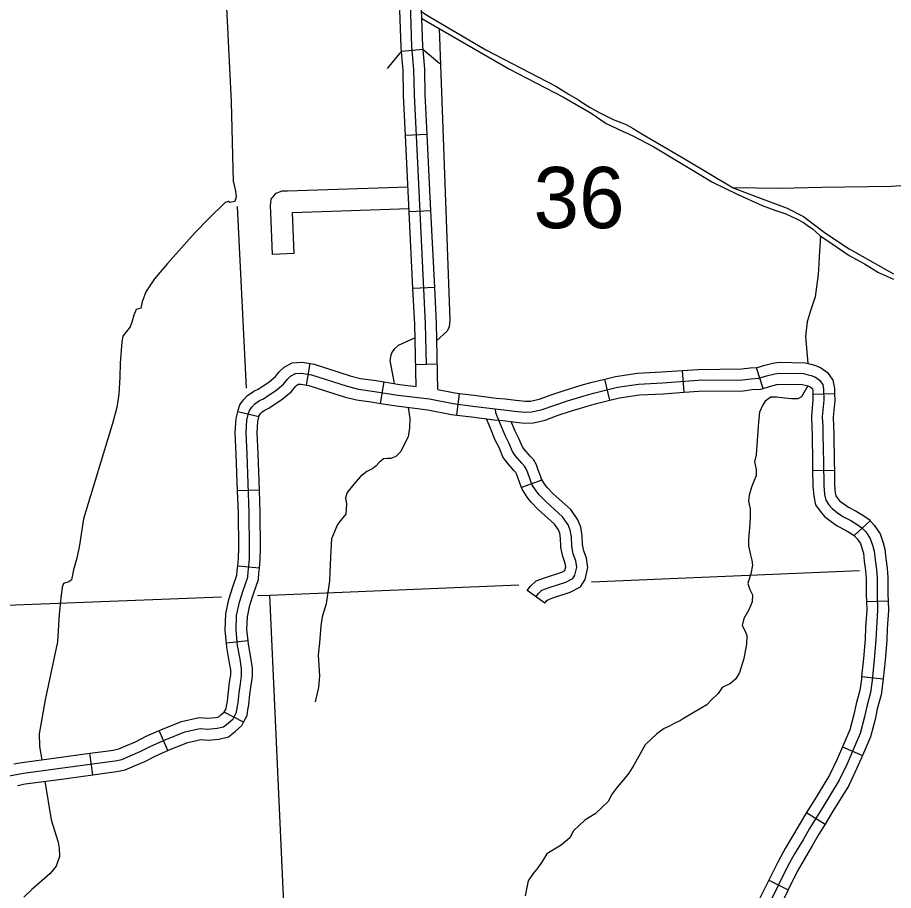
# Model space of a CAD drawing. Extents: x -5566 to 1759129, y -3726 to 731467.
# Drawn here: x -4703.72 to -4657.85, y 261.21 to 306.9 of the extents above; entities that cross this region are included whole.
import ezdxf

# ---------------------------------------------------------------- set-up
doc = ezdxf.new("R2010")
doc.units = 0
doc.layers.add('Default', color=7, linetype='Continuous')

msp = doc.modelspace()

# ---------------------------------------------------------------- linework, layer by layer
at = {"layer": 'Default'}
for p, q in [((-4682.48, 305.221), (-4683.614, 305.116)), ((-4682.265, 300.782), (-4683.403, 300.727)), ((-4682.069, 296.778), (-4683.207, 296.721)), ((-4681.871, 292.773), (-4683.009, 292.716)), ((-4688.588, 287.665), (-4688.394, 288.788)), ((-4681.731, 288.75), (-4682.87, 288.725)), ((-4664.673, 287.487), (-4665.023, 288.571)), ((-4668.808, 287.29), (-4668.89, 288.426)), ((-4684.702, 286.701), (-4684.52, 287.825)), ((-4672.692, 286.871), (-4672.963, 287.977)), ((-4680.72, 286.091), (-4680.579, 287.221)), ((-4662.073, 287.193), (-4660.934, 287.217)), ((-4691.08, 286.006), (-4692.189, 286.267)), ((-4662.081, 283.192), (-4660.942, 283.208)), ((-4676.258, 282.692), (-4677.329, 282.304)), ((-4691.054, 282.16), (-4692.193, 282.119)), ((-4659.904, 279.79), (-4659.061, 280.556)), ((-4691.047, 278.078), (-4692.181, 278.187)), ((-4676.109, 276.237), (-4677.032, 276.903)), ((-4659.263, 276.325), (-4658.125, 276.368)), ((-4691.646, 274.273), (-4692.779, 274.159)), ((-4659.513, 272.405), (-4658.38, 272.291)), ((-4691.884, 270.014), (-4692.892, 270.544)), ((-4695.841, 268.537), (-4696.304, 269.578)), ((-4699.772, 267.262), (-4699.924, 268.391)), ((-4660.514, 268.724), (-4659.471, 268.266)), ((-4662.398, 265.284), (-4661.429, 264.685)), ((-4664.381, 261.742), (-4663.361, 261.234))]:
    msp.add_line(p, q, dxfattribs=at)
for points in [[(-4692.402, 298.29), (-4692.51, 302.48), (-4692.946, 311.325), (-4692.964, 312.125), (-4692.875, 312.516)], [(-4683.577, 304.707), (-4683.633, 305.325), (-4683.728, 308.29), (-4683.736, 308.755)], [(-4682.301, 288.738), (-4682.348, 290.874), (-4682.763, 299.284), (-4682.935, 302.855), (-4682.956, 304.175), (-4683.065, 305.36), (-4683.159, 308.304), (-4683.172, 309.079)], [(-4682.442, 304.811), (-4682.496, 305.395), (-4682.59, 308.318), (-4682.597, 308.774)], [(-4682.554, 307.198), (-4682.242, 307.008), (-4679.195, 305.215), (-4675.521, 303.306), (-4674.826, 302.865), (-4674.348, 302.597), (-4674.198, 302.489), (-4673.726, 302.198), (-4673.256, 301.937), (-4672.53, 301.565), (-4671.842, 301.303), (-4671.474, 301.099), (-4671.024, 300.807), (-4670.313, 300.402), (-4668.751, 299.495), (-4666.233, 297.986)], [(-4682.543, 306.851), (-4677.95, 304.199)], [(-4681.633, 306.326), (-4681.074, 291.08), (-4681.115, 290.706), (-4681.222, 290.481), (-4681.759, 289.99)], [(-4684.343, 304.241), (-4683.614, 305.116)], [(-4682.48, 305.221), (-4681.604, 304.492)], [(-4683.403, 300.727), (-4683.504, 302.837), (-4683.525, 304.145), (-4683.577, 304.707)], [(-4682.265, 300.782), (-4682.365, 302.873), (-4682.387, 304.206), (-4682.442, 304.811)], [(-4677.95, 304.199), (-4675.131, 302.725), (-4673.671, 301.887), (-4672.884, 301.354), (-4672.045, 300.947), (-4671.495, 300.713), (-4670.392, 300.129), (-4667.321, 298.287), (-4666.034, 297.657), (-4664.718, 297.062), (-4664.054, 296.82), (-4663.487, 296.63), (-4662.89, 296.351), (-4662.564, 296.178), (-4662.37, 296.039), (-4662.091, 295.842), (-4661.709, 295.499), (-4661.049, 295.055), (-4660.16, 294.445), (-4659.372, 294.013), (-4658.623, 293.556), (-4657.848, 293.2)], [(-4683.207, 296.721), (-4683.332, 299.256), (-4683.403, 300.727)], [(-4682.069, 296.778), (-4682.194, 299.312), (-4682.265, 300.782)], [(-4692.402, 298.29), (-4692.302, 297.805), (-4692.26, 297.514), (-4692.344, 297.264), (-4692.593, 297.223), (-4692.676, 297.264), (-4692.843, 297.223), (-4693.716, 296.363), (-4694.424, 295.655), (-4695.871, 294.019), (-4696.537, 293.22), (-4697.002, 292.542), (-4697.184, 292.026), (-4697.265, 291.688), (-4697.506, 291.612), (-4697.626, 291.326), (-4697.707, 291.003), (-4697.82, 290.71), (-4698.199, 290.218), (-4698.251, 289.926), (-4698.346, 288.803), (-4698.369, 288.078), (-4698.418, 287.192), (-4698.526, 286.487), (-4698.743, 285.657), (-4700.261, 280.661), (-4700.48, 279.273), (-4700.619, 278.605), (-4700.785, 277.998), (-4700.893, 277.475), (-4701.027, 277.354), (-4701.316, 277.28), (-4701.373, 277.074), (-4701.442, 276.502), (-4701.54, 275.665), (-4701.617, 274.229), (-4702.272, 271.189), (-4702.582, 269.411), (-4702.562, 268.748), (-4702.453, 268.049)], [(-4656.186, 298.17), (-4657.966, 298.048), (-4661.596, 297.999), (-4663.798, 297.957), (-4666.233, 297.986)], [(-4689.223, 294.543), (-4690.361, 294.493), (-4690.458, 296.698), (-4690.474, 297.047), (-4690.436, 297.386), (-4690.165, 297.712), (-4689.86, 297.834), (-4689.58, 297.834), (-4683.272, 298.04)], [(-4666.233, 297.986), (-4665.054, 297.531), (-4663.41, 296.922), (-4662.56, 296.478), (-4661.41, 295.616)], [(-4691.73, 287.508), (-4692.2, 297.004)], [(-4689.223, 294.543), (-4689.318, 296.703), (-4683.216, 296.903)], [(-4683.009, 292.716), (-4683.207, 296.721)], [(-4681.871, 292.773), (-4682.069, 296.778)], [(-4661.674, 295.476), (-4661.734, 294.394), (-4661.747, 294.013), (-4661.798, 293.442), (-4661.941, 292.278), (-4662.203, 291.497), (-4662.358, 290.966), (-4662.457, 290.212), (-4662.323, 288.795)], [(-4661.41, 295.616), (-4660.163, 294.801), (-4657.844, 293.485)], [(-4682.845, 287.591), (-4682.917, 290.854), (-4683.009, 292.716)], [(-4681.702, 287.426), (-4681.779, 290.894), (-4681.871, 292.773)], [(-4682.901, 290.127), (-4683.782, 289.734), (-4683.982, 289.56), (-4684.091, 289.404), (-4684.169, 289.226), (-4684.229, 288.95), (-4683.992, 287.74)], [(-4692.189, 286.267), (-4692.17, 286.346), (-4692.069, 286.635), (-4691.877, 286.886), (-4691.679, 287.114), (-4691.335, 287.35), (-4691.118, 287.448), (-4690.854, 287.626), (-4690.554, 287.818), (-4690.204, 288.114), (-4690.008, 288.353), (-4689.762, 288.595), (-4689.328, 288.817), (-4688.818, 288.861), (-4688.394, 288.788)], [(-4688.394, 288.788), (-4688.186, 288.752), (-4686.301, 288.144), (-4685.757, 288.005), (-4684.933, 287.892), (-4684.52, 287.825)], [(-4668.89, 288.426), (-4668.093, 288.483), (-4665.791, 288.503), (-4665.351, 288.559), (-4664.997, 288.58), (-4665.023, 288.571)], [(-4665.023, 288.571), (-4664.649, 288.692), (-4664.162, 288.807), (-4663.827, 288.856), (-4662.472, 288.832), (-4662.169, 288.751), (-4661.981, 288.696), (-4661.665, 288.58), (-4661.31, 288.318), (-4661.016, 287.919), (-4660.939, 287.477), (-4660.934, 287.217)], [(-4691.644, 277.898), (-4691.626, 278.014), (-4691.573, 278.566), (-4691.563, 279.132), (-4691.582, 280.968), (-4691.692, 284.05), (-4691.747, 285.167), (-4691.706, 285.832), (-4691.623, 286.186), (-4691.561, 286.361), (-4691.435, 286.526), (-4691.297, 286.685), (-4691.054, 286.852), (-4690.839, 286.949), (-4690.541, 287.15), (-4690.215, 287.358), (-4689.796, 287.713), (-4689.587, 287.969), (-4689.425, 288.128), (-4689.168, 288.259), (-4688.842, 288.288), (-4688.322, 288.197), (-4686.459, 287.596), (-4685.866, 287.445), (-4685.017, 287.329), (-4683.797, 287.131), (-4682.146, 286.933), (-4680.901, 286.688), (-4679.878, 286.56), (-4678.704, 286.409), (-4678.245, 286.37), (-4677.692, 286.304), (-4677.146, 286.246), (-4676.786, 286.257), (-4676.239, 286.374), (-4675.588, 286.618), (-4674.925, 286.839), (-4674.042, 287.106), (-4673.553, 287.246), (-4672.297, 287.554), (-4671.2, 287.71), (-4669.949, 287.779), (-4668.07, 287.914), (-4665.752, 287.934), (-4665.298, 287.992), (-4664.891, 288.015), (-4664.496, 288.143), (-4664.055, 288.247), (-4663.79, 288.286), (-4662.552, 288.263), (-4662.322, 288.202), (-4662.159, 288.155), (-4661.938, 288.073), (-4661.717, 287.91), (-4661.554, 287.69), (-4661.508, 287.422), (-4661.496, 286.875), (-4661.578, 286.003), (-4661.554, 285.468), (-4661.543, 285.073)], [(-4672.963, 287.977), (-4672.405, 288.114), (-4671.256, 288.277), (-4669.986, 288.348), (-4668.89, 288.426)], [(-4691.08, 286.006), (-4691.075, 286.026), (-4691.054, 286.087), (-4690.994, 286.166), (-4690.915, 286.257), (-4690.774, 286.354), (-4690.561, 286.45), (-4690.228, 286.674), (-4689.876, 286.899), (-4689.388, 287.312), (-4689.165, 287.584), (-4689.087, 287.661), (-4689.008, 287.702), (-4688.867, 287.714), (-4688.588, 287.665)], [(-4688.588, 287.665), (-4688.459, 287.643), (-4686.617, 287.049), (-4685.975, 286.885), (-4685.102, 286.766), (-4684.702, 286.701)], [(-4684.52, 287.825), (-4683.717, 287.695), (-4682.845, 287.591)], [(-4676.785, 286.84), (-4676.399, 286.922), (-4675.778, 287.155), (-4675.098, 287.382), (-4674.202, 287.653), (-4673.699, 287.797), (-4672.963, 287.977)], [(-4664.673, 287.487), (-4664.343, 287.594), (-4663.948, 287.687), (-4663.754, 287.716), (-4662.632, 287.695), (-4662.475, 287.653), (-4662.337, 287.613), (-4662.211, 287.567), (-4662.125, 287.503), (-4662.093, 287.46), (-4662.076, 287.367), (-4662.073, 287.193)], [(-4681.702, 287.426), (-4680.811, 287.25), (-4680.579, 287.221)], [(-4680.579, 287.221), (-4679.807, 287.125), (-4678.644, 286.975), (-4678.187, 286.937), (-4677.628, 286.87), (-4677.125, 286.816), (-4676.855, 286.825), (-4676.785, 286.84)], [(-4672.692, 286.871), (-4672.189, 286.994), (-4671.144, 287.143), (-4669.913, 287.211), (-4668.808, 287.29)], [(-4668.808, 287.29), (-4668.047, 287.345), (-4665.713, 287.364), (-4665.246, 287.424), (-4664.786, 287.451), (-4664.673, 287.487)], [(-4662.337, 287.616), (-4662.667, 287.044), (-4662.854, 286.947), (-4663.188, 286.944), (-4663.531, 286.971), (-4663.973, 287.034), (-4664.269, 287.025), (-4664.567, 286.825), (-4664.703, 286.584), (-4664.868, 286.251), (-4664.92, 285.731), (-4665.042, 284.012), (-4665.119, 283.644)], [(-4662.073, 287.193), (-4662.066, 286.896), (-4662.148, 286.017), (-4662.124, 285.447), (-4662.112, 285.059), (-4662.087, 283.594), (-4662.081, 283.192)], [(-4660.934, 287.217), (-4660.926, 286.855), (-4661.007, 285.989), (-4660.985, 285.489), (-4660.973, 285.086), (-4660.948, 283.612), (-4660.942, 283.208)], [(-4684.702, 286.701), (-4683.876, 286.567), (-4682.235, 286.371), (-4680.992, 286.125), (-4680.72, 286.091)], [(-4676.548, 285.726), (-4676.079, 285.825), (-4675.398, 286.081), (-4674.753, 286.296), (-4673.881, 286.56), (-4673.407, 286.695), (-4672.692, 286.871)], [(-4692.193, 282.119), (-4692.261, 284.026), (-4692.318, 285.171), (-4692.271, 285.916), (-4692.189, 286.267)], [(-4683.255, 286.493), (-4683.182, 285.912), (-4683.198, 285.423), (-4683.259, 284.956), (-4683.439, 284.623), (-4683.638, 284.189), (-4683.911, 283.914), (-4684.166, 283.815), (-4684.356, 283.816), (-4684.553, 283.803), (-4684.797, 283.589), (-4684.929, 283.433), (-4685.107, 283.297), (-4685.421, 283.135), (-4685.755, 282.881), (-4686.1, 282.481), (-4686.458, 282.035), (-4686.541, 281.751), (-4686.485, 281.425), (-4686.53, 280.912), (-4686.779, 280.592), (-4686.969, 280.365), (-4687.273, 279.608), (-4687.315, 279.012), (-4687.338, 278.272), (-4687.38, 277.409), (-4687.548, 276.214), (-4687.763, 275.529), (-4687.832, 275.062), (-4687.911, 274.16), (-4687.982, 273.525), (-4687.896, 272.437), (-4687.961, 271.825), (-4688.102, 271.241), (-4688.137, 271.088)], [(-4676.571, 276.57), (-4676.438, 276.754), (-4676.254, 276.917), (-4675.877, 277.06), (-4674.999, 277.346), (-4674.632, 277.54), (-4674.53, 277.703), (-4674.428, 278.132), (-4674.479, 278.458), (-4674.612, 278.835), (-4674.693, 279.224), (-4674.713, 279.714), (-4674.775, 280.061), (-4674.887, 280.347), (-4675.173, 280.765), (-4676.059, 281.564), (-4676.396, 281.913), (-4676.565, 282.128), (-4676.78, 282.46), (-4676.872, 282.715), (-4677.001, 283.065), (-4677.065, 283.245), (-4677.163, 283.419), (-4677.303, 283.565), (-4677.658, 283.983), (-4677.797, 284.187), (-4677.983, 284.629), (-4678.181, 285.013), (-4678.442, 285.647), (-4678.669, 286.211), (-4678.691, 286.408)], [(-4691.054, 282.16), (-4691.123, 284.075), (-4691.177, 285.163), (-4691.14, 285.749), (-4691.08, 286.006)], [(-4680.72, 286.091), (-4679.95, 285.995), (-4678.764, 285.842), (-4678.303, 285.803), (-4677.756, 285.738), (-4677.167, 285.675), (-4676.717, 285.69), (-4676.548, 285.726)], [(-4677.329, 282.304), (-4677.407, 282.519), (-4677.536, 282.871), (-4677.585, 283.008), (-4677.624, 283.077), (-4677.726, 283.183), (-4678.111, 283.638), (-4678.3, 283.913), (-4678.5, 284.388), (-4678.698, 284.773), (-4678.97, 285.432), (-4679.155, 285.892)], [(-4676.258, 282.692), (-4676.337, 282.91), (-4676.465, 283.258), (-4676.544, 283.482), (-4676.703, 283.762), (-4676.88, 283.946), (-4677.204, 284.329), (-4677.295, 284.461), (-4677.467, 284.87), (-4677.663, 285.252), (-4677.869, 285.751)], [(-4661.543, 285.073), (-4661.518, 283.603), (-4661.5, 282.397), (-4661.456, 281.933), (-4661.39, 281.632), (-4661.231, 281.4), (-4661.065, 281.197), (-4660.779, 280.982), (-4660.497, 280.786), (-4660.085, 280.564), (-4659.751, 280.365), (-4659.503, 280.196), (-4659.299, 279.971), (-4659.065, 279.624), (-4658.932, 279.236), (-4658.86, 278.961), (-4658.809, 278.512), (-4658.738, 278.011), (-4658.707, 277.562), (-4658.707, 276.694), (-4658.677, 275.878), (-4658.738, 274.958), (-4658.769, 274.325), (-4658.85, 273.304), (-4658.962, 272.191), (-4659.054, 271.569), (-4659.248, 270.844), (-4659.36, 270.293), (-4659.595, 269.425), (-4659.815, 268.898), (-4660.279, 267.843), (-4660.687, 266.975), (-4661.554, 265.566), (-4662.248, 264.444), (-4662.582, 263.856), (-4663.024, 263.117), (-4663.389, 262.456), (-4664.748, 259.728)], [(-4665.119, 283.644), (-4665.029, 283.245), (-4665.029, 282.917), (-4665.159, 282.637), (-4665.286, 282.312), (-4665.395, 281.89), (-4665.43, 281.576), (-4665.358, 281.182), (-4665.36, 280.762), (-4665.364, 280.396), (-4665.438, 279.593), (-4665.435, 279.243), (-4665.354, 278.841), (-4665.268, 278.501), (-4665.23, 278.242), (-4665.322, 277.775), (-4665.447, 277.397), (-4665.481, 277.274), (-4665.373, 276.965), (-4665.227, 276.679), (-4665.239, 276.321), (-4665.423, 275.888), (-4665.69, 275.437), (-4665.778, 275.084), (-4665.61, 274.784), (-4665.519, 274.551), (-4665.543, 274.1), (-4665.687, 273.341), (-4665.908, 272.617), (-4666.102, 272.276), (-4666.384, 272.038), (-4666.81, 271.827), (-4667.032, 271.517), (-4667.412, 271.145), (-4667.619, 270.93), (-4668.847, 270.214), (-4669.007, 270.097), (-4669.334, 269.941), (-4669.573, 269.808), (-4669.861, 269.68), (-4670.235, 269.402), (-4670.843, 268.826), (-4671.441, 267.768), (-4671.698, 267.341), (-4671.997, 266.988), (-4672.317, 266.615), (-4672.584, 266.273), (-4672.787, 265.867), (-4673.126, 265.546), (-4673.466, 265.223), (-4674.002, 264.886), (-4674.6, 264.326), (-4674.802, 263.969), (-4675.253, 263.581), (-4675.678, 263.324), (-4676.006, 263.131), (-4676.252, 262.726), (-4676.462, 262.384), (-4676.719, 262.102), (-4676.981, 261.713), (-4677.131, 260.923)], [(-4662.081, 283.192), (-4662.069, 282.366), (-4662.019, 281.845), (-4661.923, 281.401), (-4661.687, 281.059), (-4661.462, 280.783), (-4661.113, 280.521), (-4660.796, 280.3), (-4660.366, 280.068), (-4660.057, 279.884), (-4659.88, 279.763), (-4659.904, 279.79)], [(-4660.942, 283.208), (-4660.931, 282.428), (-4660.892, 282.021), (-4660.857, 281.862), (-4660.775, 281.742), (-4660.667, 281.61), (-4660.445, 281.444), (-4660.198, 281.271), (-4659.804, 281.059), (-4659.444, 280.845), (-4659.127, 280.629), (-4659.061, 280.556)], [(-4674.125, 279.282), (-4674.146, 279.776), (-4674.224, 280.216), (-4674.38, 280.615), (-4674.741, 281.143), (-4675.663, 281.974), (-4675.966, 282.288), (-4676.101, 282.46), (-4676.267, 282.715), (-4676.258, 282.692)], [(-4692.181, 278.187), (-4692.142, 278.598), (-4692.133, 279.134), (-4692.151, 280.955), (-4692.193, 282.119)], [(-4691.047, 278.078), (-4691.003, 278.534), (-4690.994, 279.13), (-4691.012, 280.981), (-4691.054, 282.16)], [(-4675.264, 279.235), (-4675.281, 279.652), (-4675.326, 279.906), (-4675.394, 280.079), (-4675.605, 280.388), (-4676.455, 281.154), (-4676.826, 281.539), (-4677.029, 281.797), (-4677.293, 282.204), (-4677.329, 282.304)], [(-4659.061, 280.556), (-4658.85, 280.324), (-4658.55, 279.88), (-4658.386, 279.4), (-4658.299, 279.065), (-4658.244, 278.584), (-4658.171, 278.071), (-4658.138, 277.582), (-4658.138, 276.705), (-4658.125, 276.368)], [(-4659.904, 279.79), (-4659.748, 279.619), (-4659.579, 279.368), (-4659.478, 279.073), (-4659.422, 278.857), (-4659.374, 278.439), (-4659.305, 277.952), (-4659.277, 277.543), (-4659.277, 276.684), (-4659.263, 276.325)], [(-4677.032, 276.903), (-4676.863, 277.138), (-4676.554, 277.412), (-4676.066, 277.597), (-4675.222, 277.872), (-4675.054, 277.961), (-4675.008, 278.155), (-4675.033, 278.319), (-4675.161, 278.682), (-4675.26, 279.153), (-4675.264, 279.235)], [(-4676.109, 276.237), (-4676.013, 276.37), (-4675.954, 276.422), (-4675.688, 276.522), (-4674.776, 276.819), (-4674.23, 277.108), (-4673.997, 277.48), (-4673.848, 278.109), (-4673.924, 278.598), (-4674.062, 278.989), (-4674.126, 279.295), (-4674.125, 279.282)], [(-4692.779, 274.159), (-4692.846, 274.827), (-4692.815, 275.678), (-4692.653, 276.44), (-4692.441, 277.094), (-4692.227, 277.712), (-4692.21, 277.961), (-4692.191, 278.085), (-4692.181, 278.187)], [(-4691.646, 274.273), (-4691.705, 274.863), (-4691.681, 275.537), (-4691.551, 276.145), (-4691.361, 276.732), (-4691.101, 277.484), (-4691.077, 277.836), (-4691.06, 277.944), (-4691.047, 278.078)], [(-4704.836, 267.087), (-4703.404, 267.344), (-4701.614, 267.588), (-4698.882, 267.957), (-4698.612, 267.996), (-4698.25, 268.069), (-4697.816, 268.246), (-4697.296, 268.473), (-4696.73, 268.765), (-4695.991, 269.094), (-4694.959, 269.504), (-4694.156, 269.678), (-4693.745, 269.651), (-4693.261, 269.696), (-4692.924, 269.769), (-4692.695, 269.961), (-4692.431, 270.198), (-4692.248, 270.545), (-4692.221, 270.765), (-4692.166, 271.02), (-4692.111, 271.55), (-4692.047, 272.025), (-4691.983, 272.445), (-4691.983, 272.801), (-4692.065, 273.311), (-4692.193, 274.024), (-4692.275, 274.845), (-4692.248, 275.607), (-4692.102, 276.292), (-4691.901, 276.913), (-4691.664, 277.598), (-4691.644, 277.898)], [(-4673.659, 277.369), (-4659.631, 277.951)], [(-4691.148, 276.644), (-4690.499, 276.67), (-4677.459, 277.211)], [(-4689.765, 260.508), (-4690.499, 276.67)], [(-4738.666, 274.817), (-4731.463, 275.094), (-4730.826, 275.118), (-4693.037, 276.571)], [(-4659.263, 276.325), (-4659.247, 275.886), (-4659.307, 274.99), (-4659.337, 274.361), (-4659.417, 273.355), (-4659.513, 272.405)], [(-4658.125, 276.368), (-4658.106, 275.869), (-4658.169, 274.925), (-4658.2, 274.288), (-4658.283, 273.253), (-4658.38, 272.291)], [(-4692.892, 270.544), (-4692.8, 270.719), (-4692.783, 270.86), (-4692.729, 271.11), (-4692.677, 271.617), (-4692.611, 272.106), (-4692.553, 272.488), (-4692.553, 272.755), (-4692.627, 273.216), (-4692.758, 273.945), (-4692.779, 274.159)], [(-4691.884, 270.014), (-4691.696, 270.372), (-4691.659, 270.669), (-4691.602, 270.931), (-4691.545, 271.483), (-4691.483, 271.944), (-4691.414, 272.402), (-4691.414, 272.847), (-4691.504, 273.407), (-4691.629, 274.102), (-4691.646, 274.273)], [(-4659.513, 272.405), (-4659.528, 272.261), (-4659.613, 271.684), (-4659.803, 270.974), (-4659.915, 270.424), (-4660.135, 269.61), (-4660.339, 269.122), (-4660.514, 268.724)], [(-4658.38, 272.291), (-4658.397, 272.121), (-4658.496, 271.453), (-4658.693, 270.713), (-4658.806, 270.161), (-4659.055, 269.24), (-4659.292, 268.674), (-4659.471, 268.266)], [(-4696.304, 269.578), (-4696.212, 269.619), (-4695.126, 270.051), (-4694.198, 270.252), (-4693.753, 270.222), (-4693.349, 270.26), (-4693.182, 270.296), (-4693.069, 270.391), (-4692.887, 270.554), (-4692.892, 270.544)], [(-4695.841, 268.537), (-4695.769, 268.569), (-4694.792, 268.958), (-4694.114, 269.104), (-4693.737, 269.079), (-4693.174, 269.132), (-4692.665, 269.242), (-4692.322, 269.531), (-4691.974, 269.843), (-4691.884, 270.014)], [(-4699.924, 268.391), (-4698.962, 268.521), (-4698.71, 268.558), (-4698.416, 268.616), (-4698.038, 268.771), (-4697.54, 268.987), (-4696.977, 269.278), (-4696.304, 269.578)], [(-4703.919, 267.831), (-4703.493, 267.907), (-4701.69, 268.152), (-4699.924, 268.391)], [(-4699.772, 267.262), (-4698.803, 267.393), (-4698.515, 267.435), (-4698.085, 267.521), (-4697.595, 267.722), (-4697.051, 267.958), (-4696.483, 268.251), (-4695.841, 268.537)], [(-4660.514, 268.724), (-4660.797, 268.079), (-4661.189, 267.246), (-4662.039, 265.865), (-4662.398, 265.284)], [(-4659.471, 268.266), (-4659.76, 267.607), (-4660.185, 266.704), (-4661.069, 265.267), (-4661.429, 264.685)], [(-4703.718, 266.709), (-4703.315, 266.782), (-4701.537, 267.023), (-4699.772, 267.262)], [(-4702.282, 266.922), (-4701.958, 264.901), (-4701.595, 263.738), (-4701.54, 263.42), (-4701.519, 262.978), (-4701.686, 262.477), (-4702.008, 262.086), (-4702.962, 261.248), (-4703.39, 260.853)], [(-4662.398, 265.284), (-4662.738, 264.734), (-4663.075, 264.142), (-4663.518, 263.4), (-4663.893, 262.721), (-4664.381, 261.742)], [(-4661.429, 264.685), (-4661.758, 264.153), (-4662.09, 263.569), (-4662.53, 262.833), (-4662.884, 262.191), (-4663.361, 261.234)], [(-4664.381, 261.742), (-4665.262, 259.973), (-4665.853, 258.674), (-4666.148, 258.222)], [(-4663.361, 261.234), (-4664.234, 259.483), (-4664.852, 258.123), (-4665.195, 257.598)]]:
    msp.add_lwpolyline(points, dxfattribs=at)

# ---------------------------------------------------------------- texts
msp.add_text('36', height=3.2048, dxfattribs=at).set_placement((-4676.696, 295.874))

doc.saveas('drawing.dxf')
